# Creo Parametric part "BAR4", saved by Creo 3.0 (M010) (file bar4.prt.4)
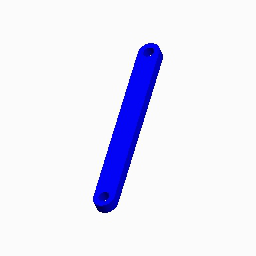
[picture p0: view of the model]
Units: millimeter Newton Second (mmNs); MM, TONNE, SECS

Created from: MMNS_PART_SOLID.PRT

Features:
  1. datum plane "RIGHT"
  2. datum plane "TOP"
  3. datum plane "FRONT"
  4. coordinate system
  5. sketch "Sketch 1"
  6. extrusion "Extrude 1"

Surfaces: 7 plane, 6 cylinder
